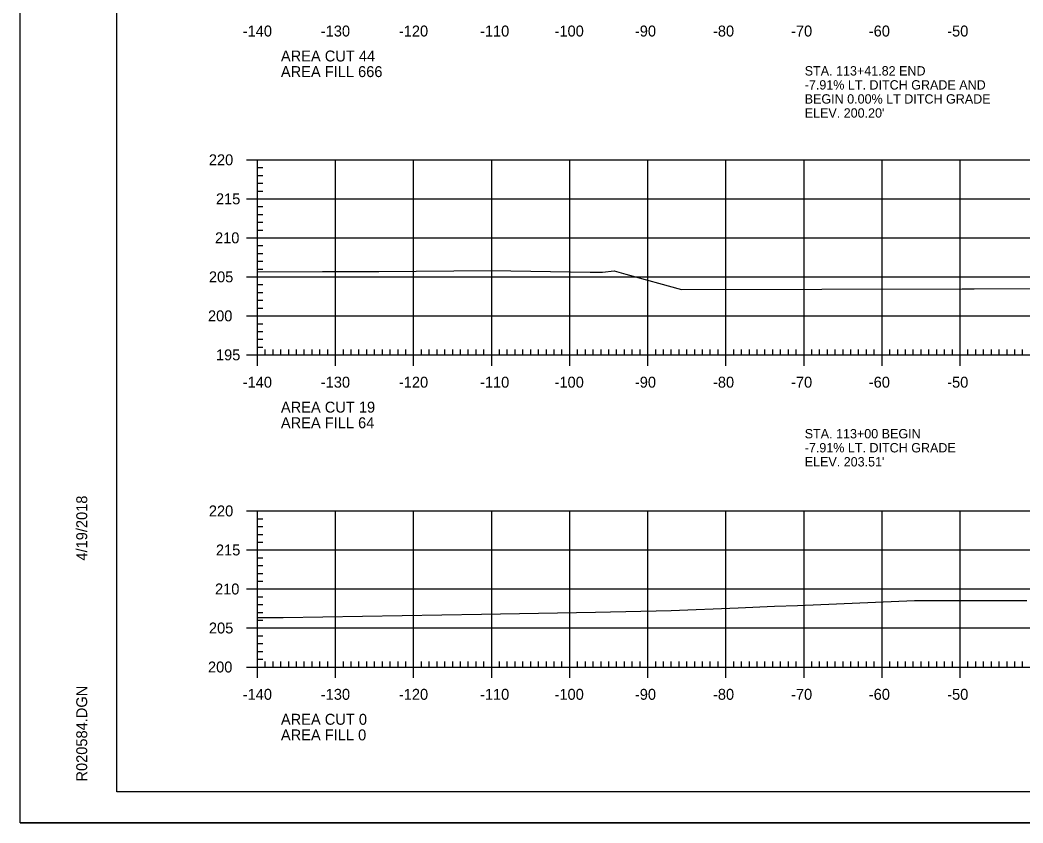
# Model space of a CAD drawing. Extents: x 1312042 to 1371461, y 379929 to 1834241.
# Drawn here: x 1371127.9 to 1371256.3, y 379928.9 to 380031.8 of the extents above; entities that cross this region are included whole.
import ezdxf

# ---------------------------------------------------------------- set-up
doc = ezdxf.new("R2010")
doc.units = 0
for name, color, linetype in [('R_Axis', 7, 'Continuous'), ('R_Axis Annot', 7, 'Continuous'), ('R_Border', 7, 'Continuous'), ('R_Drive', 7, 'Continuous'), ('R_Exist Surface', 7, 'Continuous'), ('R_Grid', 7, 'Continuous'), ('R_No Plot', 7, 'Continuous')]:
    doc.layers.add(name, color=color, linetype=linetype)

msp = doc.modelspace()

# ---------------------------------------------------------------- linework, layer by layer
at = {"layer": 'R_Axis'}
for p, q in [((1371156.88, 380013.91), (1371159.68, 380013.91)), ((1371158.28, 379988.91), (1371158.28, 380013.91)), ((1371158.28, 380012.91), (1371158.98, 380012.91)), ((1371158.28, 380011.91), (1371158.98, 380011.91)), ((1371158.28, 380010.91), (1371158.98, 380010.91)), ((1371158.28, 380009.91), (1371158.98, 380009.91)), ((1371156.88, 380008.91), (1371159.68, 380008.91)), ((1371158.28, 380007.91), (1371158.98, 380007.91)), ((1371158.28, 380006.91), (1371158.98, 380006.91)), ((1371158.28, 380005.91), (1371158.98, 380005.91)), ((1371158.28, 380004.91), (1371158.98, 380004.91)), ((1371156.88, 380003.91), (1371159.68, 380003.91)), ((1371158.28, 380002.91), (1371158.98, 380002.91)), ((1371158.28, 380001.91), (1371158.98, 380001.91)), ((1371158.28, 380000.91), (1371158.98, 380000.91)), ((1371158.28, 379999.91), (1371158.98, 379999.91)), ((1371156.88, 379998.91), (1371159.68, 379998.91)), ((1371158.28, 379997.91), (1371158.98, 379997.91)), ((1371158.28, 379996.91), (1371158.98, 379996.91)), ((1371158.28, 379995.91), (1371158.98, 379995.91)), ((1371156.88, 379993.91), (1371159.68, 379993.91)), ((1371158.28, 379994.91), (1371158.98, 379994.91)), ((1371158.28, 379992.91), (1371158.98, 379992.91)), ((1371158.28, 379991.91), (1371158.98, 379991.91)), ((1371158.28, 379990.91), (1371158.98, 379990.91)), ((1371158.28, 379987.51), (1371158.28, 379990.31)), ((1371168.28, 379987.51), (1371168.28, 379990.31)), ((1371178.28, 379987.51), (1371178.28, 379990.31)), ((1371188.28, 379987.51), (1371188.28, 379990.31)), ((1371198.28, 379987.51), (1371198.28, 379990.31)), ((1371208.28, 379987.51), (1371208.28, 379990.31)), ((1371218.28, 379987.51), (1371218.28, 379990.31)), ((1371228.28, 379987.51), (1371228.28, 379990.31)), ((1371238.28, 379987.51), (1371238.28, 379990.31)), ((1371248.28, 379987.51), (1371248.28, 379990.31)), ((1371156.88, 379988.91), (1371159.68, 379988.91)), ((1371158.28, 379989.91), (1371158.98, 379989.91)), ((1371158.28, 379988.91), (1371438.28, 379988.91)), ((1371159.28, 379988.91), (1371159.28, 379989.61)), ((1371160.28, 379988.91), (1371160.28, 379989.61)), ((1371161.28, 379988.91), (1371161.28, 379989.61)), ((1371162.28, 379988.91), (1371162.28, 379989.61)), ((1371163.28, 379988.91), (1371163.28, 379989.61)), ((1371164.28, 379988.91), (1371164.28, 379989.61)), ((1371165.28, 379988.91), (1371165.28, 379989.61)), ((1371166.28, 379988.91), (1371166.28, 379989.61)), ((1371167.28, 379988.91), (1371167.28, 379989.61)), ((1371169.28, 379988.91), (1371169.28, 379989.61)), ((1371170.28, 379988.91), (1371170.28, 379989.61)), ((1371171.28, 379988.91), (1371171.28, 379989.61)), ((1371172.28, 379988.91), (1371172.28, 379989.61)), ((1371173.28, 379988.91), (1371173.28, 379989.61)), ((1371174.28, 379988.91), (1371174.28, 379989.61)), ((1371175.28, 379988.91), (1371175.28, 379989.61)), ((1371176.28, 379988.91), (1371176.28, 379989.61)), ((1371177.28, 379988.91), (1371177.28, 379989.61)), ((1371179.28, 379988.91), (1371179.28, 379989.61)), ((1371180.28, 379988.91), (1371180.28, 379989.61)), ((1371181.28, 379988.91), (1371181.28, 379989.61)), ((1371182.28, 379988.91), (1371182.28, 379989.61)), ((1371183.28, 379988.91), (1371183.28, 379989.61)), ((1371184.28, 379988.91), (1371184.28, 379989.61)), ((1371185.28, 379988.91), (1371185.28, 379989.61)), ((1371186.28, 379988.91), (1371186.28, 379989.61)), ((1371187.28, 379988.91), (1371187.28, 379989.61)), ((1371189.28, 379988.91), (1371189.28, 379989.61)), ((1371190.28, 379988.91), (1371190.28, 379989.61)), ((1371191.28, 379988.91), (1371191.28, 379989.61)), ((1371192.28, 379988.91), (1371192.28, 379989.61)), ((1371193.28, 379988.91), (1371193.28, 379989.61)), ((1371194.28, 379988.91), (1371194.28, 379989.61)), ((1371195.28, 379988.91), (1371195.28, 379989.61)), ((1371196.28, 379988.91), (1371196.28, 379989.61)), ((1371197.28, 379988.91), (1371197.28, 379989.61)), ((1371199.28, 379988.91), (1371199.28, 379989.61)), ((1371200.28, 379988.91), (1371200.28, 379989.61)), ((1371201.28, 379988.91), (1371201.28, 379989.61)), ((1371202.28, 379988.91), (1371202.28, 379989.61)), ((1371203.28, 379988.91), (1371203.28, 379989.61)), ((1371204.28, 379988.91), (1371204.28, 379989.61)), ((1371205.28, 379988.91), (1371205.28, 379989.61)), ((1371206.28, 379988.91), (1371206.28, 379989.61)), ((1371207.28, 379988.91), (1371207.28, 379989.61)), ((1371209.28, 379988.91), (1371209.28, 379989.61)), ((1371210.28, 379988.91), (1371210.28, 379989.61)), ((1371211.28, 379988.91), (1371211.28, 379989.61)), ((1371212.28, 379988.91), (1371212.28, 379989.61)), ((1371213.28, 379988.91), (1371213.28, 379989.61)), ((1371214.28, 379988.91), (1371214.28, 379989.61)), ((1371215.28, 379988.91), (1371215.28, 379989.61)), ((1371216.28, 379988.91), (1371216.28, 379989.61)), ((1371217.28, 379988.91), (1371217.28, 379989.61)), ((1371219.28, 379988.91), (1371219.28, 379989.61)), ((1371220.28, 379988.91), (1371220.28, 379989.61)), ((1371221.28, 379988.91), (1371221.28, 379989.61)), ((1371222.28, 379988.91), (1371222.28, 379989.61)), ((1371223.28, 379988.91), (1371223.28, 379989.61)), ((1371224.28, 379988.91), (1371224.28, 379989.61)), ((1371225.28, 379988.91), (1371225.28, 379989.61)), ((1371226.28, 379988.91), (1371226.28, 379989.61)), ((1371227.28, 379988.91), (1371227.28, 379989.61)), ((1371229.28, 379988.91), (1371229.28, 379989.61)), ((1371230.28, 379988.91), (1371230.28, 379989.61)), ((1371231.28, 379988.91), (1371231.28, 379989.61)), ((1371232.28, 379988.91), (1371232.28, 379989.61)), ((1371233.28, 379988.91), (1371233.28, 379989.61)), ((1371234.28, 379988.91), (1371234.28, 379989.61)), ((1371235.28, 379988.91), (1371235.28, 379989.61)), ((1371236.28, 379988.91), (1371236.28, 379989.61)), ((1371237.28, 379988.91), (1371237.28, 379989.61)), ((1371239.28, 379988.91), (1371239.28, 379989.61)), ((1371240.28, 379988.91), (1371240.28, 379989.61)), ((1371241.28, 379988.91), (1371241.28, 379989.61)), ((1371242.28, 379988.91), (1371242.28, 379989.61)), ((1371243.28, 379988.91), (1371243.28, 379989.61)), ((1371244.28, 379988.91), (1371244.28, 379989.61)), ((1371245.28, 379988.91), (1371245.28, 379989.61)), ((1371246.28, 379988.91), (1371246.28, 379989.61)), ((1371247.28, 379988.91), (1371247.28, 379989.61)), ((1371249.28, 379988.91), (1371249.28, 379989.61)), ((1371250.28, 379988.91), (1371250.28, 379989.61)), ((1371251.28, 379988.91), (1371251.28, 379989.61)), ((1371252.28, 379988.91), (1371252.28, 379989.61)), ((1371253.28, 379988.91), (1371253.28, 379989.61)), ((1371254.28, 379988.91), (1371254.28, 379989.61)), ((1371255.28, 379988.91), (1371255.28, 379989.61)), ((1371256.28, 379988.91), (1371256.28, 379989.61)), ((1371156.88, 379968.91), (1371159.68, 379968.91)), ((1371158.28, 379948.91), (1371158.28, 379968.91)), ((1371158.28, 379967.91), (1371158.98, 379967.91)), ((1371158.28, 379966.91), (1371158.98, 379966.91)), ((1371158.28, 379965.91), (1371158.98, 379965.91)), ((1371158.28, 379964.91), (1371158.98, 379964.91)), ((1371156.88, 379963.91), (1371159.68, 379963.91)), ((1371158.28, 379962.91), (1371158.98, 379962.91)), ((1371158.28, 379961.91), (1371158.98, 379961.91)), ((1371158.28, 379960.91), (1371158.98, 379960.91)), ((1371158.28, 379959.91), (1371158.98, 379959.91)), ((1371156.88, 379958.91), (1371159.68, 379958.91)), ((1371158.28, 379957.91), (1371158.98, 379957.91)), ((1371158.28, 379956.91), (1371158.98, 379956.91)), ((1371158.28, 379955.91), (1371158.98, 379955.91)), ((1371158.28, 379954.91), (1371158.98, 379954.91)), ((1371156.88, 379953.91), (1371159.68, 379953.91)), ((1371158.28, 379952.91), (1371158.98, 379952.91)), ((1371158.28, 379951.91), (1371158.98, 379951.91)), ((1371158.28, 379950.91), (1371158.98, 379950.91)), ((1371158.28, 379947.51), (1371158.28, 379950.31)), ((1371168.28, 379947.51), (1371168.28, 379950.31)), ((1371178.28, 379947.51), (1371178.28, 379950.31)), ((1371188.28, 379947.51), (1371188.28, 379950.31)), ((1371198.28, 379947.51), (1371198.28, 379950.31)), ((1371208.28, 379947.51), (1371208.28, 379950.31)), ((1371218.28, 379947.51), (1371218.28, 379950.31)), ((1371228.28, 379947.51), (1371228.28, 379950.31)), ((1371238.28, 379947.51), (1371238.28, 379950.31)), ((1371248.28, 379947.51), (1371248.28, 379950.31)), ((1371156.88, 379948.91), (1371159.68, 379948.91)), ((1371158.28, 379949.91), (1371158.98, 379949.91)), ((1371158.28, 379948.91), (1371438.28, 379948.91)), ((1371159.28, 379948.91), (1371159.28, 379949.61)), ((1371160.28, 379948.91), (1371160.28, 379949.61)), ((1371161.28, 379948.91), (1371161.28, 379949.61)), ((1371162.28, 379948.91), (1371162.28, 379949.61)), ((1371163.28, 379948.91), (1371163.28, 379949.61)), ((1371164.28, 379948.91), (1371164.28, 379949.61)), ((1371165.28, 379948.91), (1371165.28, 379949.61)), ((1371166.28, 379948.91), (1371166.28, 379949.61)), ((1371167.28, 379948.91), (1371167.28, 379949.61)), ((1371169.28, 379948.91), (1371169.28, 379949.61)), ((1371170.28, 379948.91), (1371170.28, 379949.61)), ((1371171.28, 379948.91), (1371171.28, 379949.61)), ((1371172.28, 379948.91), (1371172.28, 379949.61)), ((1371173.28, 379948.91), (1371173.28, 379949.61)), ((1371174.28, 379948.91), (1371174.28, 379949.61)), ((1371175.28, 379948.91), (1371175.28, 379949.61)), ((1371176.28, 379948.91), (1371176.28, 379949.61)), ((1371177.28, 379948.91), (1371177.28, 379949.61)), ((1371179.28, 379948.91), (1371179.28, 379949.61)), ((1371180.28, 379948.91), (1371180.28, 379949.61)), ((1371181.28, 379948.91), (1371181.28, 379949.61)), ((1371182.28, 379948.91), (1371182.28, 379949.61)), ((1371183.28, 379948.91), (1371183.28, 379949.61)), ((1371184.28, 379948.91), (1371184.28, 379949.61)), ((1371185.28, 379948.91), (1371185.28, 379949.61)), ((1371186.28, 379948.91), (1371186.28, 379949.61)), ((1371187.28, 379948.91), (1371187.28, 379949.61)), ((1371189.28, 379948.91), (1371189.28, 379949.61)), ((1371190.28, 379948.91), (1371190.28, 379949.61)), ((1371191.28, 379948.91), (1371191.28, 379949.61)), ((1371192.28, 379948.91), (1371192.28, 379949.61)), ((1371193.28, 379948.91), (1371193.28, 379949.61)), ((1371194.28, 379948.91), (1371194.28, 379949.61)), ((1371195.28, 379948.91), (1371195.28, 379949.61)), ((1371196.28, 379948.91), (1371196.28, 379949.61)), ((1371197.28, 379948.91), (1371197.28, 379949.61)), ((1371199.28, 379948.91), (1371199.28, 379949.61)), ((1371200.28, 379948.91), (1371200.28, 379949.61)), ((1371201.28, 379948.91), (1371201.28, 379949.61)), ((1371202.28, 379948.91), (1371202.28, 379949.61)), ((1371203.28, 379948.91), (1371203.28, 379949.61)), ((1371204.28, 379948.91), (1371204.28, 379949.61)), ((1371205.28, 379948.91), (1371205.28, 379949.61)), ((1371206.28, 379948.91), (1371206.28, 379949.61)), ((1371207.28, 379948.91), (1371207.28, 379949.61)), ((1371209.28, 379948.91), (1371209.28, 379949.61)), ((1371210.28, 379948.91), (1371210.28, 379949.61)), ((1371211.28, 379948.91), (1371211.28, 379949.61)), ((1371212.28, 379948.91), (1371212.28, 379949.61)), ((1371213.28, 379948.91), (1371213.28, 379949.61)), ((1371214.28, 379948.91), (1371214.28, 379949.61)), ((1371215.28, 379948.91), (1371215.28, 379949.61)), ((1371216.28, 379948.91), (1371216.28, 379949.61)), ((1371217.28, 379948.91), (1371217.28, 379949.61)), ((1371219.28, 379948.91), (1371219.28, 379949.61)), ((1371220.28, 379948.91), (1371220.28, 379949.61)), ((1371221.28, 379948.91), (1371221.28, 379949.61)), ((1371222.28, 379948.91), (1371222.28, 379949.61)), ((1371223.28, 379948.91), (1371223.28, 379949.61)), ((1371224.28, 379948.91), (1371224.28, 379949.61)), ((1371225.28, 379948.91), (1371225.28, 379949.61)), ((1371226.28, 379948.91), (1371226.28, 379949.61)), ((1371227.28, 379948.91), (1371227.28, 379949.61)), ((1371229.28, 379948.91), (1371229.28, 379949.61)), ((1371230.28, 379948.91), (1371230.28, 379949.61)), ((1371231.28, 379948.91), (1371231.28, 379949.61)), ((1371232.28, 379948.91), (1371232.28, 379949.61)), ((1371233.28, 379948.91), (1371233.28, 379949.61)), ((1371234.28, 379948.91), (1371234.28, 379949.61)), ((1371235.28, 379948.91), (1371235.28, 379949.61)), ((1371236.28, 379948.91), (1371236.28, 379949.61)), ((1371237.28, 379948.91), (1371237.28, 379949.61)), ((1371239.28, 379948.91), (1371239.28, 379949.61)), ((1371240.28, 379948.91), (1371240.28, 379949.61)), ((1371241.28, 379948.91), (1371241.28, 379949.61)), ((1371242.28, 379948.91), (1371242.28, 379949.61)), ((1371243.28, 379948.91), (1371243.28, 379949.61)), ((1371244.28, 379948.91), (1371244.28, 379949.61)), ((1371245.28, 379948.91), (1371245.28, 379949.61)), ((1371246.28, 379948.91), (1371246.28, 379949.61)), ((1371247.28, 379948.91), (1371247.28, 379949.61)), ((1371249.28, 379948.91), (1371249.28, 379949.61)), ((1371250.28, 379948.91), (1371250.28, 379949.61)), ((1371251.28, 379948.91), (1371251.28, 379949.61)), ((1371252.28, 379948.91), (1371252.28, 379949.61)), ((1371253.28, 379948.91), (1371253.28, 379949.61)), ((1371254.28, 379948.91), (1371254.28, 379949.61)), ((1371255.28, 379948.91), (1371255.28, 379949.61)), ((1371256.28, 379948.91), (1371256.28, 379949.61))]:
    msp.add_line(p, q, dxfattribs=at)
at = {"layer": 'R_Border'}
for p, q in [((1371140.28, 379932.91), (1371140.28, 380138.37)), ((1371140.28, 379932.91), (1371140.28, 379932.91)), ((1371456.46, 379932.91), (1371140.28, 379932.91))]:
    msp.add_line(p, q, dxfattribs=at)
at = {"layer": 'R_Exist Surface'}
for points in [[(1371158.28, 379999.57), (1371166.61, 379999.58), (1371173.82, 379999.58), (1371188.23, 379999.72), (1371200.9, 379999.53), (1371202.31, 379999.52), (1371202.46, 379999.52), (1371203.97, 379999.66), (1371205.46, 379999.26), (1371212.58, 379997.3), (1371248.54, 379997.37), (1371249.08, 379997.37), (1371250.09, 379997.37), (1371260.04, 379997.42)], [(1371158.28, 379955.24), (1371161.57, 379955.27), (1371186.97, 379955.69), (1371201.58, 379955.93), (1371211.26, 379956.17), (1371219.85, 379956.49), (1371224.51, 379956.72), (1371227.44, 379956.81), (1371242.43, 379957.45), (1371256.8, 379957.44)]]:
    msp.add_lwpolyline(points, dxfattribs=at)
at = {"layer": 'R_Grid'}
for p, q in [((1371158.28, 380013.91), (1371438.28, 380013.91)), ((1371158.28, 379988.91), (1371158.28, 380013.91)), ((1371168.28, 379988.91), (1371168.28, 380013.91)), ((1371178.28, 379988.91), (1371178.28, 380013.91)), ((1371188.28, 379988.91), (1371188.28, 380013.91)), ((1371198.28, 379988.91), (1371198.28, 380013.91)), ((1371208.28, 379988.91), (1371208.28, 380013.91)), ((1371218.28, 379988.91), (1371218.28, 380013.91)), ((1371228.28, 379988.91), (1371228.28, 380013.91)), ((1371238.28, 379988.91), (1371238.28, 380013.91)), ((1371248.28, 379988.91), (1371248.28, 380013.91)), ((1371158.28, 380008.91), (1371438.28, 380008.91)), ((1371158.28, 380003.91), (1371438.28, 380003.91)), ((1371158.28, 379998.91), (1371438.28, 379998.91)), ((1371158.28, 379993.91), (1371438.28, 379993.91)), ((1371158.28, 379988.91), (1371438.28, 379988.91)), ((1371158.28, 379968.91), (1371438.28, 379968.91)), ((1371158.28, 379948.91), (1371158.28, 379968.91)), ((1371168.28, 379948.91), (1371168.28, 379968.91)), ((1371178.28, 379948.91), (1371178.28, 379968.91)), ((1371188.28, 379948.91), (1371188.28, 379968.91)), ((1371198.28, 379948.91), (1371198.28, 379968.91)), ((1371208.28, 379948.91), (1371208.28, 379968.91)), ((1371218.28, 379948.91), (1371218.28, 379968.91)), ((1371228.28, 379948.91), (1371228.28, 379968.91)), ((1371238.28, 379948.91), (1371238.28, 379968.91)), ((1371248.28, 379948.91), (1371248.28, 379968.91)), ((1371158.28, 379963.91), (1371438.28, 379963.91)), ((1371158.28, 379958.91), (1371438.28, 379958.91)), ((1371158.28, 379953.91), (1371438.28, 379953.91)), ((1371158.28, 379948.91), (1371438.28, 379948.91))]:
    msp.add_line(p, q, dxfattribs=at)
at = {"layer": 'R_No Plot'}
msp.add_line((1371127.88, 379928.93), (1371461.21, 379928.93), dxfattribs=at)
for points in [[(1371127.87, 380142.26), (1371461.21, 380142.26), (1371461.21, 379928.93), (1371127.87, 379928.93)], [(1371374.2, 380138.37), (1371374.2, 380128.49), (1371409.93, 380128.49), (1371409.93, 380125.57), (1371433.13, 380125.57), (1371433.13, 380101.24), (1371456.46, 380101.24), (1371456.46, 379932.91), (1371140.28, 379932.91), (1371140.28, 380138.37)]]:
    msp.add_lwpolyline(points, close=True, dxfattribs=at)

# ---------------------------------------------------------------- texts
at = {"layer": 'R_Axis Annot'}
for s, p in [('-140', (1371156.39, 380029.71)), ('-130', (1371166.39, 380029.71)), ('-120', (1371176.39, 380029.71)), ('-110', (1371186.78, 380029.71)), ('-100', (1371196.33, 380029.71)), ('-90', (1371206.62, 380029.71)), ('-80', (1371216.62, 380029.71)), ('-70', (1371226.62, 380029.71)), ('-60', (1371236.58, 380029.71)), ('-50', (1371246.62, 380029.71)), ('AREA CUT 44', (1371161.28, 380026.51)), ('AREA FILL 666', (1371161.28, 380024.51)), ('220', (1371152.05, 380013.21)), ('215', (1371152.96, 380008.21)), ('210', (1371152.84, 380003.21)), ('205', (1371152.06, 379998.21)), ('200', (1371151.94, 379993.21)), ('195', (1371152.96, 379988.21)), ('-140', (1371156.39, 379984.71)), ('-130', (1371166.39, 379984.71)), ('-120', (1371176.39, 379984.71)), ('-110', (1371186.78, 379984.71)), ('-100', (1371196.33, 379984.71)), ('-90', (1371206.62, 379984.71)), ('-80', (1371216.62, 379984.71)), ('-70', (1371226.62, 379984.71)), ('-60', (1371236.58, 379984.71)), ('-50', (1371246.62, 379984.71)), ('AREA CUT 19', (1371161.28, 379981.51)), ('AREA FILL 64', (1371161.28, 379979.51)), ('220', (1371152.05, 379968.21)), ('215', (1371152.96, 379963.21)), ('210', (1371152.84, 379958.21)), ('205', (1371152.06, 379953.21)), ('200', (1371151.94, 379948.21)), ('-140', (1371156.39, 379944.71)), ('-130', (1371166.39, 379944.71)), ('-120', (1371176.39, 379944.71)), ('-110', (1371186.78, 379944.71)), ('-100', (1371196.33, 379944.71)), ('-90', (1371206.62, 379944.71)), ('-80', (1371216.62, 379944.71)), ('-70', (1371226.62, 379944.71)), ('-60', (1371236.58, 379944.71)), ('-50', (1371246.62, 379944.71)), ('AREA CUT 0', (1371161.28, 379941.51)), ('AREA FILL 0', (1371161.28, 379939.51))]:
    msp.add_text(s, height=1.4, dxfattribs=at).set_placement(p)
at = {"layer": 'R_Border'}
for s, p in [('4/19/2018', (1371136.47, 379962.55)), ('R020584.DGN', (1371136.47, 379934.23))]:
    msp.add_text(s, height=1.4, rotation=90, dxfattribs=at).set_placement(p)
at = {"layer": 'R_Drive'}
for s, p in [('STA. 113+41.82 END', (1371228.37, 380024.71)), ('-7.91% LT. DITCH GRADE AND', (1371228.37, 380022.91)), ('BEGIN 0.00% LT DITCH GRADE', (1371228.37, 380021.11)), ("ELEV. 200.20'", (1371228.37, 380019.31)), ('STA. 113+00 BEGIN', (1371228.37, 379978.21)), ('-7.91% LT. DITCH GRADE', (1371228.37, 379976.41)), ("ELEV. 203.51'", (1371228.37, 379974.61))]:
    msp.add_text(s, height=1.2, dxfattribs=at).set_placement(p)

doc.saveas('drawing.dxf')
